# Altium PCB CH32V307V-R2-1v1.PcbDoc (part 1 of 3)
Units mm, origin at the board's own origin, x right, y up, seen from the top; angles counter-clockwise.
Board outline 80 x 115 mm, 2 copper layers (Top Layer, Bottom Layer); 122 components, 134 nets, 559 pads, 721 vias.
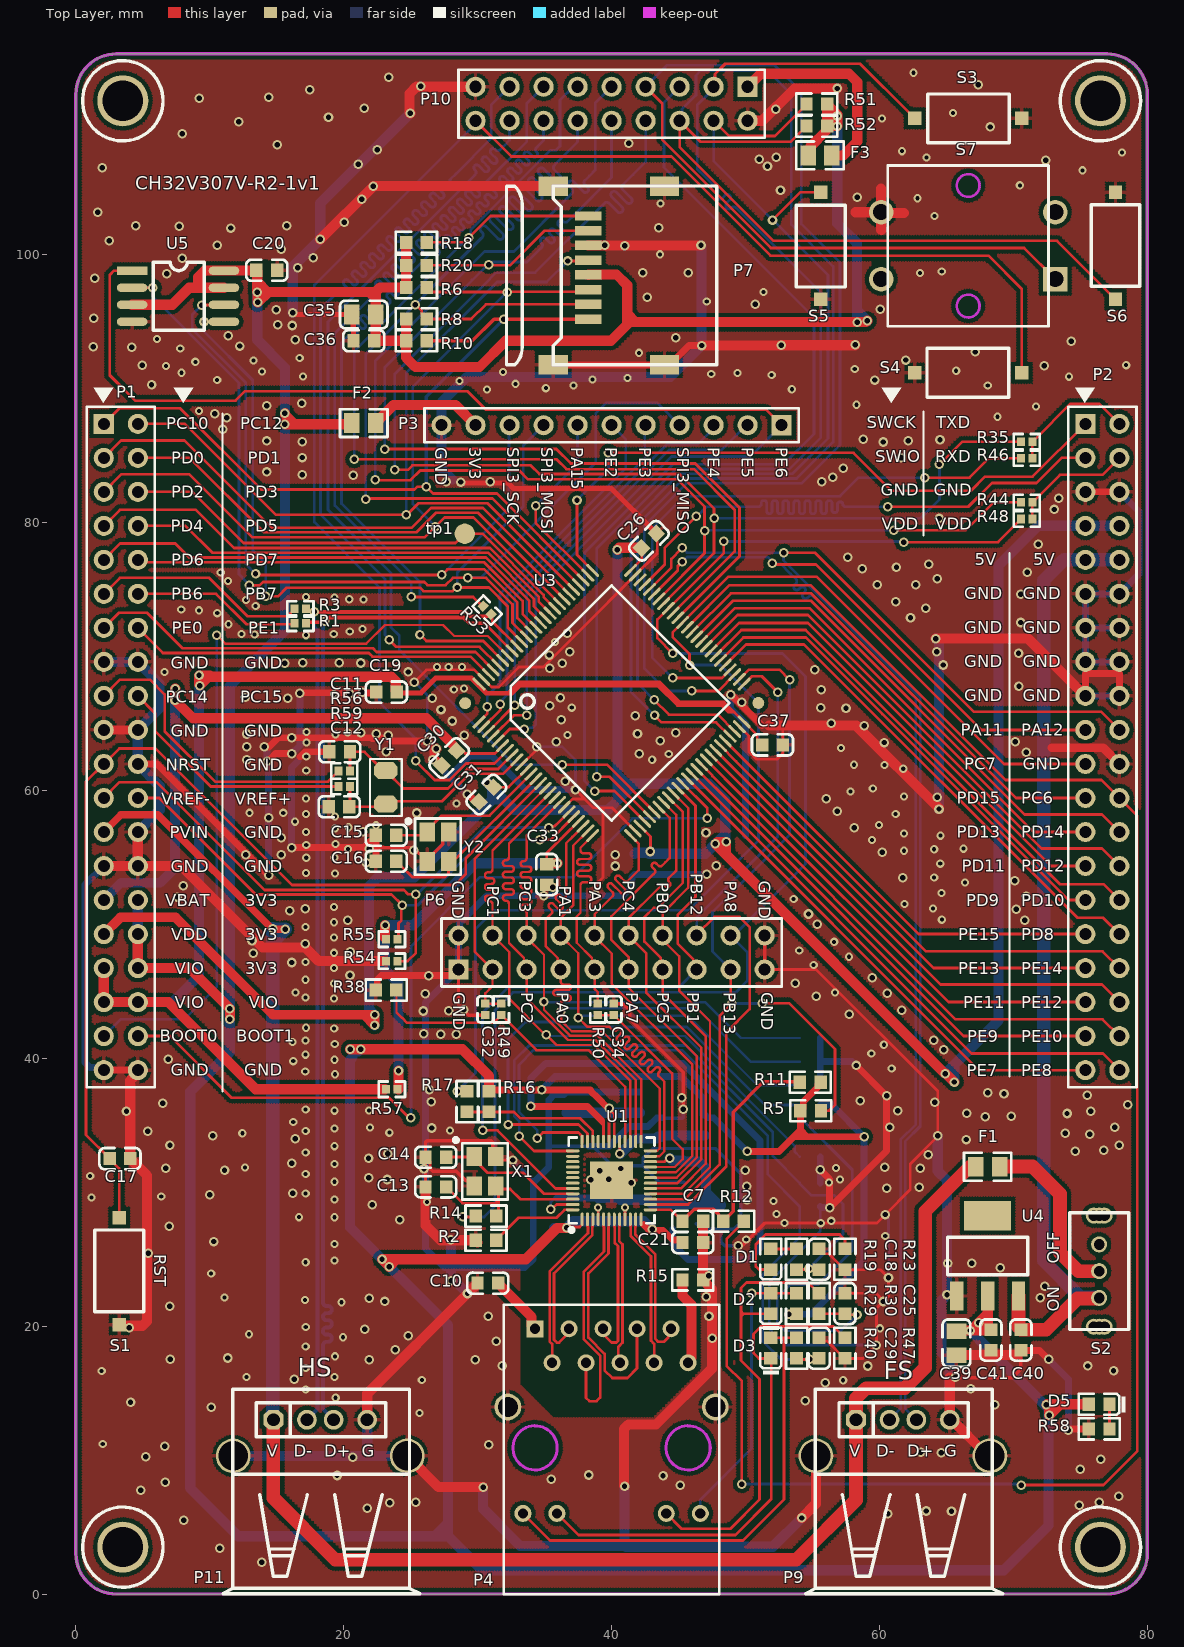
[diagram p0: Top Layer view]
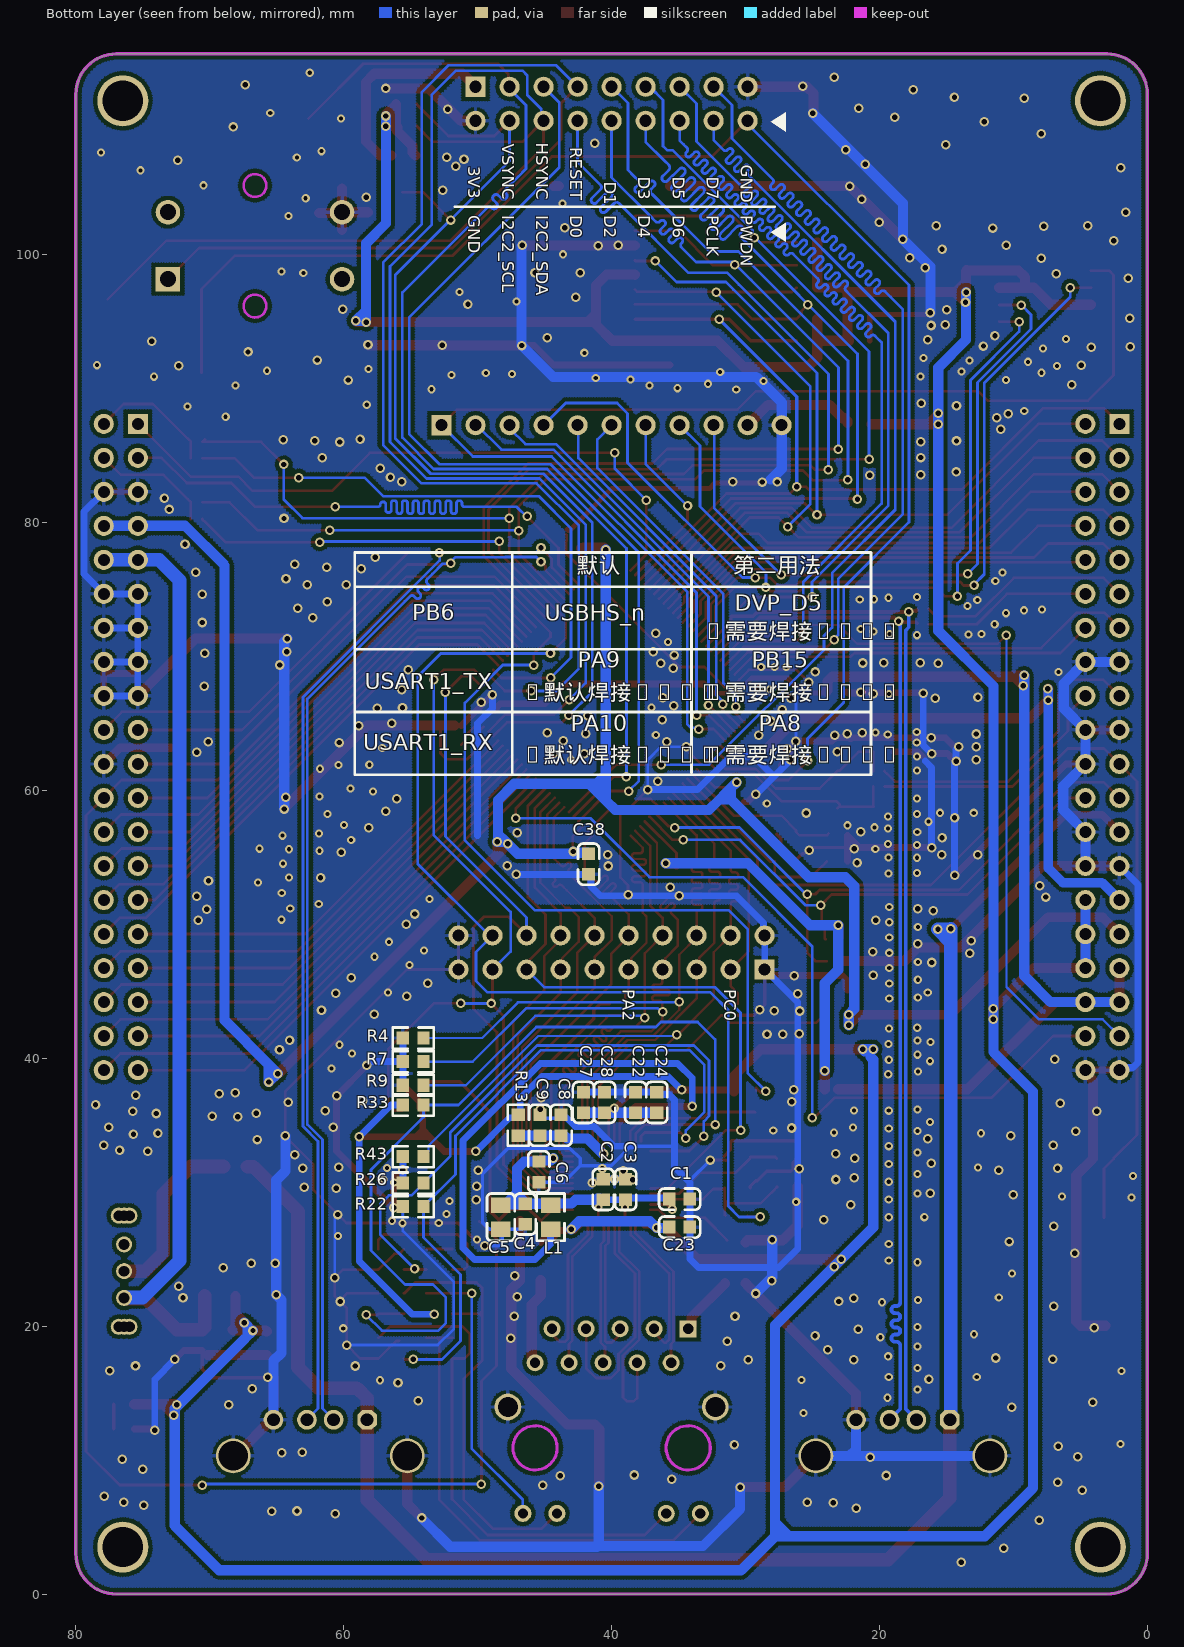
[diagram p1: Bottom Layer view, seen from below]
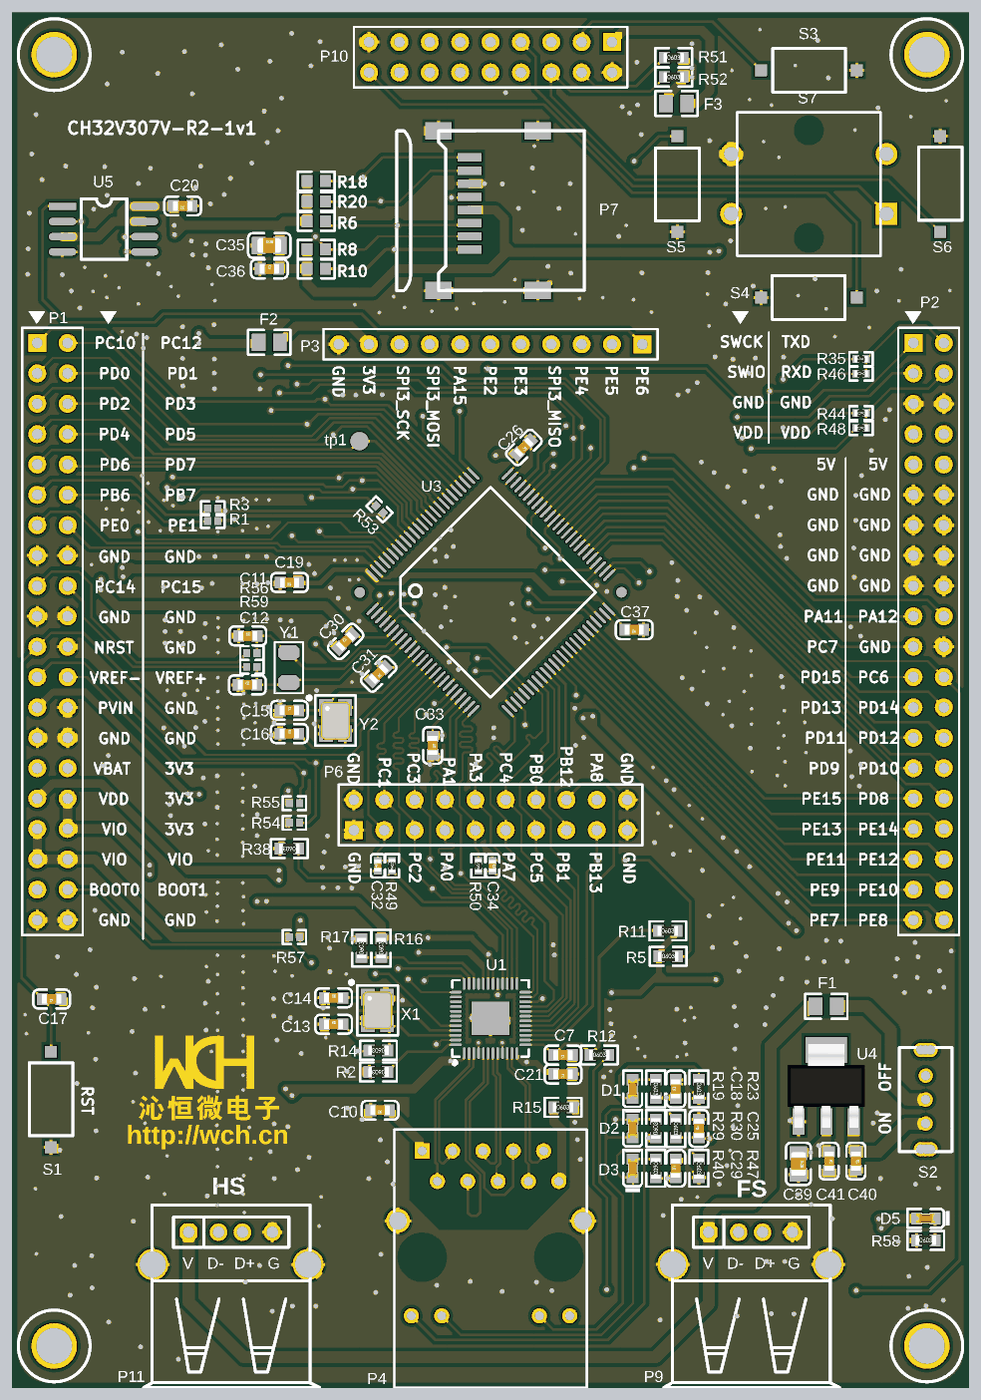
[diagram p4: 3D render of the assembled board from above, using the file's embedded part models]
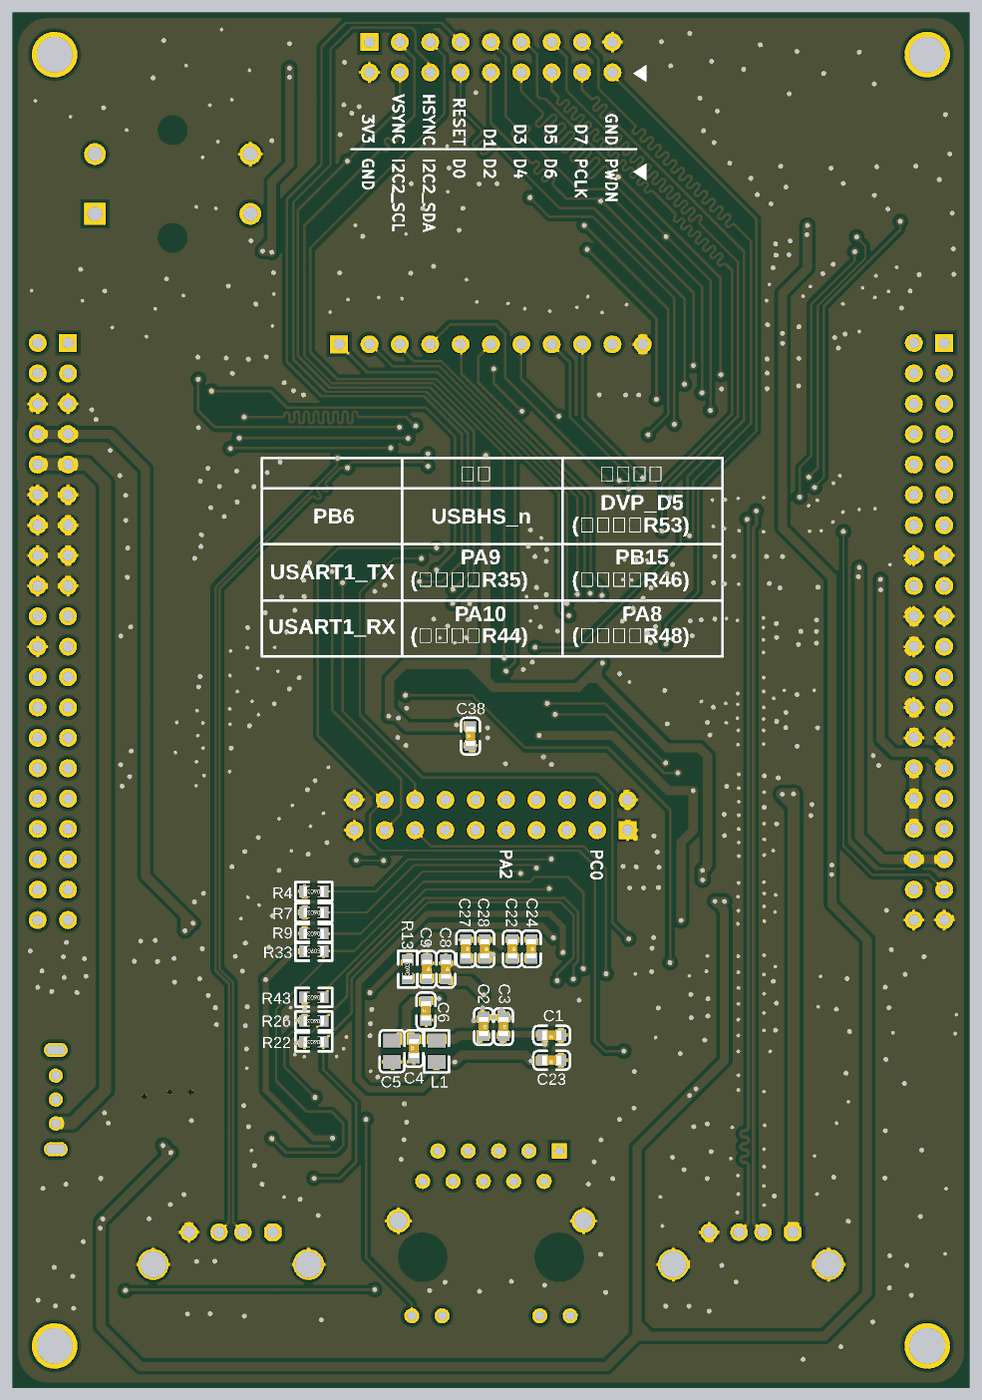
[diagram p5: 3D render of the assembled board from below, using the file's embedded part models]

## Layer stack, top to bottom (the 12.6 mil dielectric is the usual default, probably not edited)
Top Solder: solder mask 0.0102, Solder Resist, Dk 3.5
Top Layer: signal copper 0.0356
Dielectric 1: dielectric 0.32, FR-4, Dk 4.8
Bottom Layer: signal copper 0.0356
Bottom Solder: solder mask 0.0102, Solder Resist, Dk 3.5

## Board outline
0,3 0,112 cw(c3,112) 3,115 77.007,115 77,115 cw(c77,112) 80,112 80,2.999 80,3 cw(c77,3) 77,0 3,0 cw(c3,3)

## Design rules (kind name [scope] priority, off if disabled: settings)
Clearance Clearance_2 [InPolygon] p1: gap=0.305 ignorepadtopadclearanceinfootprint=FALSE
Clearance [All] p2: gap=0.127 ignorepadtopadclearanceinfootprint=FALSE except(0.178: Arc-Via Track-Via SMDPad-Via THPad-Via Via-Via Via-Fill Via-Poly Via-Region Via-Text Via-Hole)
ComponentClearance [All] p1 off: gap=0.254 collisioncheckmode=3 verticalgap=0.254 showdistances=FALSE
DiffPairsRouting [All] p1: maxlimit=0.254 minlimit=0.127 mostfreqgap=0.254 toplayer_minwidth=0.152 toplayer_maxwidth=0.381 toplayer_prefwidth=0.381 bottomlayer_minwidth=0.152 bottomlayer_maxwidth=0.381 bottomlayer_prefwidth=0.381 maxuncoupledlength=12.7
MinimumSolderMaskSliver [All] p1 off: minsoldermaskwidth=0.254
PolygonConnect PolygonConnect_1 [IsVia] p1: connectstyle=Direct reliefconductorwidth=0.254 reliefentries=4 polygonreliefangle="90 Angle" airgapwidth=0.254
PolygonConnect [All] p2: connectstyle=Relief reliefconductorwidth=0.254 reliefentries=4 polygonreliefangle="90 Angle" airgapwidth=0.254
RoutingVias [All] p1: holewidth=0.711 width=1.27 viastyle="Through Hole" minholewidth=0.305 minwidth=0.61 maxholewidth=0.711 maxwidth=1.27
SilkToSilkClearance [All] p1 off: silktosilkclearance=0.254
SilkToSolderMaskClearance [IsPad] p1 off: minsilkscreentomaskgap=0.254 clearancetoexposedcopper=TRUE
SolderMaskExpansion [All] p1: expansion=0.102 istentingtop=FALSE
Width [All] p1: maxlimit=2.54 minlimit=0.127 preferedwidth=0.254
25 further rules are at their usual default settings.

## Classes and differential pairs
differential pair USB1D: +USB1D_p -USB1D_n
differential pair USB2D: +USB2D_p -USB2D_n
differential pair MDI3: +MDI3_p -MDI3_n
differential pair MDI2: +MDI2_p -MDI2_n
differential pair MDI1: +MDI1_p -MDI1_n
differential pair MDI0: +MDI0_p -MDI0_n

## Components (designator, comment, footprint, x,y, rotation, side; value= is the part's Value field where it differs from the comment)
C1 "100nF" 0603_C 34.921,29.489 r0 bottom
C2 "100nF" 0603_C 40.623,30.217 r270 bottom
C3 "100nF" 0603_C 38.953,30.217 r270 bottom
C4 "100nF" 0603_C 46.444,28.377 r90 bottom
C5 "22uF" 0805_C#1 48.271,27.252 r90 bottom
C6 "100nF" 0603_C 45.433,31.527 r90 bottom
C7 "100nF" 0603_C 46.062,27.833 r180 top
C8 "100nF" 0603_C 43.773,35.004 r270 bottom
C9 "4.7uF" 0603_C 45.357,35.004 r270 bottom
C10 "100nF" 0603_C 30.756,23.212 r180 top
C11 "12pF" 0603_C 19.698,62.889 r0 top
C12 "12pF" 0603_C 19.657,58.786 r0 top
C13 "27pF" 0603_C 26.873,30.404 r0 top
C14 "27pF" 0603_C 26.873,32.614 r0 top
C15 "20pF" 0603_C 23.167,56.655 r0 top
C16 "20pF" 0603_C 23.167,54.719 r0 top
C17 "100nF" 0603_C 3.285,32.513 r180 top
C18 "100nF" 0603_C 55.495,24.995 r90 top
C19 "100nF" 0603_C 23.186,67.348 r180 top
C20 "100nF" 0603_C 14.251,98.843 r180 top
C21 "100nF" 0603_C 46.062,26.241 r180 top
C22 "100nF" 0603_C 38.206,36.708 r270 bottom
C23 "100nF" 0603_C 34.921,27.397 r0 bottom
C24 "4.7uF" 0603_C 36.628,36.708 r270 bottom
C25 "100nF" 0603_C 57.427,21.691 r90 top
C26 "100nF" 0603_C 42.788,78.647 r225 top
C27 "100nF" 0603_C 42.099,36.708 r270 bottom
C28 "4.7uF" 0603_C 40.521,36.708 r270 bottom
C29 "100nF" 0603_C 55.495,18.359 r90 top
C30 "100nF" 0603_C 27.879,62.42 r45 top
C31 "100nF" 0603_C 30.646,59.701 r225 top
C32 "NC" 0402_C 30.564,43.656 r90 top
C33 "100nF" 0603_C 35.157,53.724 r270 top
C34 "NC" 0402_C 40.165,43.656 r270 top
C35 "10uF" 0805_C#2 21.492,95.537 r0 top
C36 "0.1uF" 0603_C 21.498,93.583 r0 top
C37 "100nF" 0603_C 52.014,63.403 r180 top
C38 "100nF" 0603_C 41.718,54.502 r90 bottom
C39 "10uF" 0805_C#2 65.749,18.729 r270 top
C40 "100nF" 0603_C 70.563,18.964 r270 top
C41 "100nF" 0603_C 68.318,18.964 r270 top
D1 "蓝灯 0603" 0603_LED_S1 51.886,24.995 r90 top
D2 "黄灯 0805" 0603_LED_S1 51.886,21.691 r90 top
D3 "翠绿 0805" 0603_LED_S1 51.886,18.359 r90 top
D5 "蓝灯 0603" 0603_LED_S1 76.408,14.168 r180 top
F1 "500mA" 0805 67.191,31.903 r0 top
F2 "200mA" 0805 22.382,87.434 r180 top
F3 "100mA" 0805 56.447,107.419 r180 top
L1 "22uH" 0805 44.546,27.252 r90 bottom
P1 "Header 20X2" HDR2X20 2.081,87.38 r270 top
P2 "Header 20X2" HDR2X20 75.379,87.38 r270 top
P3 "Header 11" HDR1X11 52.7,87.274 r180 top
P4 "HR911130C" RJ45-1G 34.283,19.807 r180 top locked
P6 "Header 10X2" HDR2X10 28.57,46.634 r0 top
P7 "TF CARD" TF103 38.253,95.212 r180 top
P9 "USB" USBAF 58.253,13.012 r0 top
P10 "Header 9X2" HDR2X9 50.16,112.547 r180 top
P11 "USB" USBAF 14.747,13.012 r0 top
R1 "0Ω (0R0) ±1%" 0402 17.186,72.489 r180 top
R2 "2.49K 1%" 0603_R 30.619,26.416 r180 top
R3 "0Ω (0R0) ±1%" 0402 17.186,73.562 r180 top
R4 "4.7K" 0603_R 54.814,41.515 r0 bottom
R5 "4.7K" 0603_R 54.865,36.086 r0 top
R6 "47K" 0603_R 25.422,97.549 r180 top
R7 "4.7K" 0603_R 54.814,39.753 r0 bottom
R8 "47K" 0603_R 25.422,95.212 r180 top
R9 "4.7K" 0603_R 54.814,37.992 r0 bottom
R10 "47K" 0603_R 25.422,93.583 r180 top
R11 "4.7K" 0603_R 54.831,38.216 r0 top
R12 "0Ω" 0603_R 49.105,27.833 r0 top
R13 "0Ω" 0603_R 46.97,35.004 r90 bottom
R14 "0Ω" 0603_R 30.619,28.219 r180 top
R15 "0Ω" 0603_R 46.062,23.455 r0 top
R16 "4.7K" 0603_R 30.856,36.77 r90 top
R17 "0Ω(NC)" 0603_R 29.205,36.77 r90 top
R18 "47K" 0603_R 25.422,100.926 r180 top
R19 "0Ω" 0603_R 53.817,24.995 r270 top
R20 "47K" 0603_R 25.422,99.213 r180 top
R22 "4.7K" 0603_R 54.814,28.93 r0 bottom
R23 "510Ω" 0603_R 57.427,24.995 r270 top
R26 "4.7K" 0603_R 54.814,30.681 r0 bottom
R29 "510Ω" 0603_R 53.817,21.691 r90 top
R30 "0Ω" 0603_R 55.495,21.691 r270 top
R33 "4.7K" 0603_R 54.814,36.513 r180 bottom
R35 "0Ω (0R0) ±1%" 0402_R 70.991,86.037 r180 top
R38 "4.7K" 0603_R 23.167,45.098 r180 top
R40 "0Ω" 0603_R 53.817,18.359 r270 top
R43 "4.7K" 0603_R 54.814,32.656 r0 bottom
R44 "0Ω (0R0) ±1%" 0402_R 70.991,81.518 r180 top
R46 "0Ω (0R0) ±1%" 0402_R 70.991,84.811 r180 top
R47 "510Ω" 0603_R 57.427,18.359 r270 top
R48 "0Ω (0R0) ±1%" 0402_R 70.991,80.265 r180 top
R49 "0Ω" 0402_R 31.758,43.656 r90 top
R50 "0Ω" 0402_R 38.971,43.656 r90 top
R51 "10KΩ (1002) ±1%" 0603_R 55.322,111.252 r0 top
R52 "10KΩ (1002) ±1%" 0603_R 55.322,109.615 r0 top
R53 "0Ω (0R0) ±1%" 0402 31.008,73.16 r135 top
R54 "0R" 0402 23.167,47.26 r0 top
R55 "0R" 0402 23.167,48.891 r0 top
R56 "0Ω (0R0) ±1%" 0402 20.468,61.452 r180 top
R57 "0R" 0402 23.167,37.691 r0 top
R58 "470Ω (4700) ±1%" 0603_R 76.408,12.329 r0 top
R59 "0Ω (0R0) ±1%" 0402 20.468,60.293 r180 top
S1 "RST#" SMD_6.1x3.65x2.5mm-KEY 3.233,20.106 r90 top
S2 "SW SPDT" "Horizontal Slide Switch_8.7x4.4mm-2D" 78.603,19.756 r90 top
S3 "up" SMD_6.1x3.65x2.5mm-KEY 62.626,110.182 r0 top
S4 "down" SMD_6.1x3.65x2.5mm-KEY 70.626,91.182 r180 top
S5 "left" SMD_6.1x3.65x2.5mm-KEY 55.627,104.674 r270 top
S6 "right" SMD_6.1x3.65x2.5mm-KEY 77.626,96.674 r90 top
S7 "OK" KEYD 73.126,98.183 r180 top locked
tp1 "test-point" POINT 29.031,79.174 r0 top
U1 "RTL8211FS" QFN-48_6x6x04P 40,30.886 r0 top
U3 "CH32V307V" LQFP100 30.101,65.118 r315 top
U4 "LM1117" SOT-223 68.081,25.254 r270 top
U5 "W25Q32JV" SOIC-8_208mil 4.196,98.811 r270 top
X1 "25MHz" SMD-3225_4P 30.546,31.566 r270 top
Y1 "32768Hz" FC-135 23.137,61.474 r270 top
Y2 "8MHz" SMD-3225_4P 27.027,55.803 r270 top
? "" HOLE 76.5,3.5 r0 top
? "" HOLE 3.5,3.5 r0 top
? "" HOLE 3.5,111.5 r0 top
? "" HOLE 76.5,111.5 r0 top

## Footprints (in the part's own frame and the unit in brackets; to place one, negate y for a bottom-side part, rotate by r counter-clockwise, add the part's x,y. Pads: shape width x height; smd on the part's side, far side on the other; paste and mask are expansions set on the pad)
0402 [mm]
  rect 0.6x0.65 smd mask+0.051: 1(0,0) 2(0.85,0)
  silkscreen extent -0.55,-0.58 1.4,0.57
0402_C [mm]
  rect 0.6x0.65 smd mask+0.051: 1(-0.425,0) 2(0.425,0)
  silkscreen extent -0.97,-0.58 0.98,0.58, body extent -0.48,-0.3 0.52,0.3, height 0.2
0402_R [mm]
  rect 0.6x0.65 smd mask+0.051: 1(-0.425,0) 2(0.425,0)
  silkscreen extent -0.98,-0.58 0.98,0.58, body extent -0.57,-0.27 0.58,0.28, height 0.41
0603_C [mm]
  rect 0.93x0.98 smd: 1(-0.77,0) 2(0.77,0)
  silkscreen extent -1.53,-0.79 1.54,0.79, body extent -0.8,-0.4 0.8,0.4, height 0.3
0603_LED_S1 [mm]
  rect 0.93x0.98 smd: A(0.77,0) K(-0.77,0)
  silkscreen extent -1.97,-0.79 1.54,0.79, body extent -0.8,-0.4 0.8,0.4, height 0.6
0603_R [mm]
  rect 0.93x0.98 smd: 1(-0.77,0) 2(0.77,0)
  silkscreen extent -1.53,-0.79 1.54,0.79, body extent -0.85,-0.4 0.85,0.4, height 0.56
0805 [mm]
  rect 1.16x1.47 smd: 1(0,0) 2(1.78,0)
  silkscreen extent -0.88,-1.04 2.66,1.03
0805_C#1 [mm]
  rect 1.16x1.47 smd: 1(0,0) 2(1.78,0)
  silkscreen extent -0.88,-1.04 2.66,1.03
0805_C#2 [mm]
  rect 1.16x1.47 smd: 1(-0.89,0) 2(0.89,0)
  silkscreen extent -1.77,-1.04 1.77,1.04, body extent -1,-0.62 1,0.63, height 0.77
FC-135 [mil]
  oct 50x70 smd: 1(0,0) 2(98.43,0)
  silkscreen extent -35,-47 133,47
HDR1X11 [mm] "Connector; Header; 11 Position"
  rect 1.5x1.5 hole 0.9: 1(0,0)
  round 1.5 hole 0.9: 2(2.54,0) 3(5.08,0) 4(7.62,0) 5(10.16,0) 6(12.7,0) 7(15.24,0) 8(17.78,0) 9(20.32,0) 10(22.86,0) 11(25.4,0)
  silkscreen extent -1.27,-1.27 26.67,1.27
HDR2X9 [mm] "Connector; Header; 9x2 Position"
  rect 1.5x1.5 hole 0.9: 1(0,0)
  round 1.5 hole 0.9: 2(0,2.54) 3(2.54,0) 4(2.54,2.54) 5(5.08,0) 6(5.08,2.54) 7(7.62,0) 8(7.62,2.54) 9(10.16,0) 10(10.16,2.54) 11(12.7,0) 12(12.7,2.54) 13(15.24,0) 14(15.24,2.54) 15(17.78,0) 16(17.78,2.54) 17(20.32,0) 18(20.32,2.54)
  silkscreen extent -1.27,-1.27 21.59,3.81
HDR2X10 [mm] "Connector; Header; 10x2 Position"
  rect 1.5x1.5 hole 0.9: 1(0,0)
  round 1.5 hole 0.9: 2(0,2.54) 3(2.54,0) 4(2.54,2.54) 5(5.08,0) 6(5.08,2.54) 7(7.62,0) 8(7.62,2.54) 9(10.16,0) 10(10.16,2.54) 11(12.7,0) 12(12.7,2.54) 13(15.24,0) 14(15.24,2.54) 15(17.78,0) 16(17.78,2.54) 17(20.32,0) 18(20.32,2.54) 19(22.86,0) 20(22.86,2.54)
  silkscreen extent -1.27,-1.27 24.13,3.81
HDR2X20 [mm] "Connector; Header; 20x2 Position"
  rect 1.5x1.5 hole 0.9: 1(0,0)
  round 1.5 hole 0.9: 2(0,2.54) 3(2.54,0) 4(2.54,2.54) 5(5.08,0) 6(5.08,2.54) 7(7.62,0) 8(7.62,2.54) 9(10.16,0) 10(10.16,2.54) 11(12.7,0) 12(12.7,2.54) 13(15.24,0) 14(15.24,2.54) 15(17.78,0) 16(17.78,2.54) 17(20.32,0) 18(20.32,2.54) 19(22.86,0) 20(22.86,2.54) 21(25.4,0) 22(25.4,2.54) 23(27.94,0) 24(27.94,2.54) 25(30.48,0) 26(30.48,2.54) 27(33.02,0) 28(33.02,2.54) 29(35.56,0) 30(35.56,2.54) 31(38.1,0) 32(38.1,2.54) 33(40.64,0) 34(40.64,2.54) 35(43.18,0) 36(43.18,2.54) 37(45.72,0) 38(45.72,2.54) 39(48.26,0) 40(48.26,2.54)
  silkscreen extent -1.27,-1.27 49.53,3.81
HOLE [mm]
  round 3.81 hole 3: 0(0,0)
  silkscreen extent -3,-3 3,3
"Horizontal Slide Switch_8.7x4.4mm-2D" [mm]
  round 1.2 hole 0.8: 0(0.2,2.6) 0(0.2,2.2) 0(0.2,1.8) 0(8.5,1.8) 0(8.5,2.2) 0(8.5,2.6) 1(4.35,2.2) 2(2.35,2.2) 3(6.35,2.2)
  silkscreen extent 0,0 8.7,4.4
KEYD [mm]
  rect 1.829x1.829 hole 1.2: 1(0,0)
  round 1.829 hole 1.2: 2(0,-5) 3(13,-5) 4(13,0)
  Keep-Out Layer circle w0.2: c6.5,-6.991 r0.85
  Keep-Out Layer circle w0.2: c6.5,2.009 r0.85
  silkscreen extent 0.5,-8.49 12.5,3.51
LQFP100 [mil]
  round 35 smd: 0(-68,10) 0(541.18,620)
  rect 9x50 smd: 1(0,0)
  oval 9x50 smd: 2(19.69,0) 3(39.37,0) 4(59.06,0) 5(78.74,0) 6(98.43,0) 7(118.11,0) 8(137.8,0) 9(157.48,0) 10(177.17,0) 11(196.85,0) 12(216.54,0) 13(236.22,0) 14(255.91,0) 15(275.59,0) 16(295.28,0) 17(314.96,0) 18(334.64,0) 19(354.33,0) 20(374.01,0) 21(393.7,0) 22(413.38,0) 23(433.07,0) 24(452.75,0) 25(472.44,0) 51(472.44,629.92) 52(452.75,629.92) 53(433.07,629.92) 54(413.39,629.92) 55(393.7,629.92) 56(374.02,629.92) 57(354.33,629.92) 58(334.65,629.92) 59(314.96,629.92) 60(295.27,629.92) 61(275.59,629.92) 62(255.9,629.92) 63(236.22,629.92) 64(216.54,629.92) 65(196.85,629.92) 66(177.17,629.92) 67(157.48,629.92) 68(137.8,629.92) 69(118.11,629.92) 70(98.43,629.92) 71(78.74,629.92) 72(59.06,629.92) 73(39.37,629.92) 74(19.69,629.92) 75(0,629.92)
  oval 50x9 smd: 26(551.18,78.74) 27(551.18,98.43) 28(551.18,118.11) 29(551.18,137.8) 30(551.18,157.48) 31(551.18,177.17) 32(551.18,196.85) 33(551.18,216.54) 34(551.18,236.22) 35(551.18,255.91) 36(551.18,275.59) 37(551.18,295.28) 38(551.18,314.96) 39(551.18,334.65) 40(551.18,354.33) 41(551.18,374.02) 42(551.18,393.7) 43(551.18,413.39) 44(551.18,433.07) 45(551.18,452.76) 46(551.18,472.44) 47(551.18,492.13) 48(551.18,511.81) 49(551.18,531.5) 50(551.18,551.18) 76(-78.74,551.18) 77(-78.74,531.5) 78(-78.74,511.81) 79(-78.74,492.13) 80(-78.74,472.44) 81(-78.74,452.76) 82(-78.74,433.07) 83(-78.74,413.39) 84(-78.74,393.7) 85(-78.74,374.02) 86(-78.74,354.33) 87(-78.74,334.65) 88(-78.74,314.96) 89(-78.74,295.28) 90(-78.74,275.59) 91(-78.74,255.91) 92(-78.74,236.22) 93(-78.74,216.54) 94(-78.74,196.85) 95(-78.74,177.17) 96(-78.74,157.48) 97(-78.74,137.8) 98(-78.74,118.11) 99(-78.74,98.43) 100(-78.74,78.74)
  silkscreen extent -8,70 481,560
POINT [mil] "测试点"
  round 60 smd: 1(0,0)
QFN-48_6x6x04P [mm]
  rect 3.2x2.8 smd mask+0.051: 0(0,0)
  oval 0.22x1 smd mask+0.051: 1(-2.2,-2.9) 2(-1.8,-2.9) 3(-1.4,-2.9) 4(-1,-2.9) 5(-0.6,-2.9) 6(-0.2,-2.9) 7(0.2,-2.9) 8(0.6,-2.9) 9(1,-2.9) 10(1.4,-2.9) 11(1.8,-2.9) 12(2.2,-2.9) 25(2.2,2.9) 26(1.8,2.9) 27(1.4,2.9) 28(1,2.9) 29(0.6,2.9) 30(0.2,2.9) 31(-0.2,2.9) 32(-0.6,2.9) 33(-1,2.9) 34(-1.4,2.9) 35(-1.8,2.9) 36(-2.2,2.9)
  oval 1x0.22 smd mask+0.051: 13(2.9,-2.2) 14(2.9,-1.8) 15(2.9,-1.4) 16(2.9,-1) 17(2.9,-0.6) 18(2.9,-0.2) 19(2.9,0.2) 20(2.9,0.6) 21(2.9,1) 22(2.9,1.4) 23(2.9,1.8) 24(2.9,2.2) 37(-2.9,2.2) 38(-2.9,1.8) 39(-2.9,1.4) 40(-2.9,1) 41(-2.9,0.6) 42(-2.9,0.2) 43(-2.9,-0.2) 44(-2.9,-0.6) 45(-2.9,-1) 46(-2.9,-1.4) 47(-2.9,-1.8) 48(-2.9,-2.2)
  silkscreen extent -3.2,-3.85 3.2,3.2
RJ45-1G [mil]
  round 78.74 hole 59.06: 0(-529.99,229.92) 0(79.85,229.92)
  rect 50x50 hole 30: 1(0,0)
  round 50 hole 30: 2(-50,100) 3(-100,0) 4(-150,100) 5(-200,0) 6(-250,100) 7(-300,0) 8(-350,100) 9(-400,0) 10(-450,100) 11(35.76,542.91) 12(-64.24,542.91) 13(-385.9,542.91) 14(-485.9,542.91)
  Keep-Out Layer circle w9: c0,350 r65
  Keep-Out Layer circle w9: c-450,350 r65
  silkscreen extent -542,-70 92,780
SMD-3225_4P [mm]
  rect 1.4x1.15 smd: 1(-1.1,-0.8) 2(1.1,-0.8) 3(1.1,0.8) 4(-1.1,0.8)
  silkscreen extent -2.48,-2.32 2.1,1.7, body extent -1.6,-1.25 1.6,1.25, height 0.61
SMD_6.1x3.65x2.5mm-KEY [mm]
  rect 1x1 smd: 1(0,0) 2(8,0)
  silkscreen extent 0.98,-1.82 7.08,1.82
SOIC-8_208mil [mil]
  rect 24x90 smd: 1(0,0)
  oval 24x90 smd: 2(50,0) 3(100,0) 4(150,0) 5(150,270) 6(100,270) 7(50,270) 8(0,270)
  silkscreen extent -25,62 175,212
SOT-223 [mm]
  rect 2.2x1 smd: 1(3,-2.3) 2(3,0) 3(3,2.3)
  rect 2.2x3.5 smd: 2(-3,0)
  silkscreen extent -1.4,-3 1.4,3, body extent -3.49,-3.24 3.49,3.24, height 1.64
TF103 [mm]
  rect 2x0.7 smd: 1(0.003,0.011) 2(0.003,-1.089) 3(0.003,-2.189) 4(0.003,-3.289) 5(0.003,-4.389) 6(0.003,-5.489) 7(0.003,-6.589) 8(0.003,-7.689)
  rect 2.2x1.45 smd: 10(-5.697,3.436) 10(-5.697,-9.914) 10(2.603,3.436) 10(2.603,-9.914)
  silkscreen extent -9.6,-9.92 6.1,3.44
USBAF [mil]
  round 102.36 hole 86.61: 0(-118.11,-106.3) 0(393.7,-106.3)
  oct 58x58 hole 38: 1(0,0)
  round 58 hole 38: 2(98.43,0) 3(177.17,0) 4(275.59,0)
  silkscreen extent -148,-511 431,90

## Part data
C1 C2 C3 C4 C5 C6 C7 C8 C9 C10 C11 C12 C13 C14 C15 C16 C17 C18 C19 C20 C21 C22 C23 C24 C25 C26 C27 C28 C29 C30 C31 C33 C37 C38 C39 C40 C41: library part CAP, "Capacitor"
C32 C34: library part "0603 2.7pF (2R7) 0.25pF 50V", "贴片电容", Package=0603, SuppliersPartNumber=C16149
C35 C36: library part Cap, "Capacitor"
D1 D5: library part "0603 蓝灯", "发光二极管", Package=0603, SuppliersPartNumber=C72041
D2: library part "0805 黄灯", "发光二极管", Package=0805, SuppliersPartNumber=C2296
D3: library part "0805 翠绿", "发光二极管", Package=0805, SuppliersPartNumber=C2297
F1 F2 F3: library part "Fuse 1", "Fuse"
L1: library part Inductor, "Inductor"
P1 P2: "Header, 20-Pin, Dual row"
P3: "Header, 11-Pin"
P6: "Header, 10-Pin, Dual row"
P7: library part TF_自弹
P9 P11: "USB Port"
P10: "Header, 9-Pin, Dual row"
R1 R3 R35 R44 R46 R48 R53 R56 R59: library part "0402 0Ω (0R0) 1%", "贴片电阻", Package=0402, SuppliersPartNumber=C17168
R2 R4 R5 R7 R9 R11 R12 R13 R14 R15 R16 R17 R19 R22 R23 R26 R29 R30 R33 R38 R40 R43 R47: library part Res
R6 R8 R10 R18 R20 R49 R50: library part Res2, "Resistor"
R51 R52: library part "0603 10KΩ (1002) 1%", "贴片电阻", Package=0603, SuppliersPartNumber=C25804
R54 R55 R57: library part R
R58: library part "0603 470Ω (4700) 1%", "贴片电阻", Package=0603, SuppliersPartNumber=C23179
S1 S3 S4 S5 S6 S7: library part KEY1
tp1: "测试点"
U1: library part RTL8211FS(I), "千兆以太网物理层芯片"
U3: "RISC-V FPU HD-MCU, 144MHz, USB_480M, USB OTG, 1000M Ethernet MAC, 2*CAN, FSMC+DVP"
U4: library part 6219P33M
U5: library part Pro89C.tmp_25F512_2
X1: library part XTAL-2P, "2脚无源脚晶振"
Y1 Y2: library part XTAL, "Crystal Oscillator"

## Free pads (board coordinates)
  round 0.711 hole 0.406: 2(39.782,30.987)

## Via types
v1: diameter 0.711, hole 0.406, Top Layer to Bottom Layer, tented both sides, 507 vias
v2: diameter 0.61, hole 0.305, Top Layer to Bottom Layer, tented both sides, 214 vias

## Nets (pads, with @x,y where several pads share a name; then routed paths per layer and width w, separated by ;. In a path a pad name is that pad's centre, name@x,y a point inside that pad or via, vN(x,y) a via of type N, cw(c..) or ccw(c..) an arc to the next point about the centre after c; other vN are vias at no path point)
3V3: C20.2 C21.2 C22.2 C23.2 C24.2 C27.2 C28.2 C35.2 C36.2 C39.1 C41.1 D5.A F2.2 F3.2 P1.30 P1.32 P1.34 P7.4 R5.1 R6.2 R8.2 R10.2 R11.2 R13.2 R16.2 R18.2 R20.2 R29.1 R33.1 R51.2 R52.2 U1.1 U1.12 U1.30 U1.31 U4.2@68.081,22.254 U5.3 U5.7 U5.8 | length 486.5
  Top Layer w0.203: v1(36.646,27.34) 36.713,27.407 37.615,27.407 37.8,27.592 U1.1@37.8,27.986 ; 39.304,36.693 v1@39.8,36.196 ; U1.31@39.8,33.786 v1@39.8,36.196 ; U1.30@40.2,33.786 40.203,33.79 40.203,35.793 v1@39.8,36.196
  Top Layer w0.508: R16.2@30.856,37.54 30.957,37.642 34.134,37.642 38.431,37.642 38.355,37.642 ; v1(34.768,37.642) 38.355,37.642 ; v1@39.79,36.206 39.79,36.227 39.659,36.358 39.638,36.358 39.043,36.953 38.355,37.642 ; 42.376,27.583 42.624,27.335 42.807,27.152 43.842,27.152 44.567,26.427 45.106,26.427 C21.2@45.292,26.241 ; v1(50.128,33.049) 52.494,33.049 53.583,34.138 ; R11.2@55.601,38.216 55.39,38.005 55.39,37.818 54.306,36.733 54.306,36.297 R5.1@54.095,36.086 54.095,34.65 ; v1(58.85,34.138) 54.607,34.138 ; 53.583,34.138 54.095,34.65 ; 53.583,34.138 54.607,34.138 ; 54.095,34.65 54.607,34.138
  Top Layer w0.762: U5.3@4.196,96.271 7.193,96.271 8.463,97.541 U5.7@11.054,97.541 ; P1.32@4.621,49.28 P1.34@4.621,46.74 8.465,46.74 v1(11.488,43.718) 11.497,43.709 v1@11.497,42.97 ; 9.126,97.746 9.126,98.329 9.625,98.827 C20.2@13.465,98.827 ; C20.2@13.481,98.843 C20.2@13.465,98.827 ; v1(15.607,88.182) v1@15.607,88.043 ; 16.204,87.446 v1@15.607,88.043 ; v1(20.469,40.683) 28.856,40.683 30.856,38.683 R16.2@30.856,37.54 ; F2.2@20.602,87.351 v1(15.607,87.351) v1@15.607,88.043 ; C36.2@22.269,93.583 C36.2@22.288,93.583 ; R8.2@24.652,95.212 R10.2@24.652,93.583 ; R18.2@24.652,100.901 R20.2@24.652,99.213 R6.2@24.652,97.549 24.586,97.549 24.568,97.568 22.717,97.568 22.382,97.233 22.382,97.216 ; v1(36.646,27.34) 35.941,27.34 33.599,24.999 23.941,24.999 ; P7.4@38.25,98.501 38.275,98.526 40.368,98.526 41.163,97.731 41.163,95.593 ; F3.2@54.652,107.419 54.866,107.633 54.866,108.105 56.008,109.247 56.008,109.531 R52.2@56.092,109.615 ; R51.2@56.092,111.252 R51.2@56.092,111.227 ; v1(59.096,95.069) 59.001,94.974 v1(58.333,94.974) 42.624,94.974 41.782,94.974 ; C39.1@65.749,19.619 65.807,19.676 v1(66.778,19.676) v1@66.832,19.676 ; U4.2@68.081,22.254 68.081,20.925 ; D5.A@75.638,14.168 73.499,14.168 ; C20.2@13.465,98.827 13.534,98.759 13.534,97.987 ; v1(13.534,97.216) 14.305,97.216 ; v1(13.534,97.216) 13.534,97.987 ; v1(13.534,97.216) 13.574,97.176 v1(13.574,96.44) 14.35,97.216 ; 13.534,97.987 14.305,97.216 ; 14.305,97.216 14.35,97.216 ; 14.35,97.216 21.943,97.216 ; 21.943,97.216 22.382,97.216 ; 21.943,97.216 22.382,96.777 ; C36.2@22.288,93.583 R10.2@24.652,93.583 ; C36.2@22.288,93.583 22.382,93.678 C35.2@22.382,95.537 22.382,96.777 ; 22.382,96.777 22.382,97.216 ; 23.941,24.999 v1(22.857,24.999) 23.386,24.47 v1(23.386,24.444) 23.941,24.999 ; R10.2@24.652,93.583 24.652,92.324 25.35,91.625 30.14,91.625 32.101,93.587 39.955,93.587 41.163,94.795 ; 41.163,94.795 41.163,95.593 ; 41.163,94.795 41.342,94.974 41.782,94.974 ; 41.163,95.593 41.782,94.974 ; R52.2@56.092,109.615 v1(56.857,109.615) 56.856,109.616 v1(56.856,110.364) ; R52.2@56.092,109.615 56.092,110.114 ; 56.092,110.114 R51.2@56.092,111.227 ; 56.092,110.114 56.341,110.364 v1(56.856,110.364) ; R51.2@56.092,111.227 56.856,110.463 v1(56.856,110.364) ; v1@66.832,19.676 68.26,19.676 C41.1@68.318,19.734 68.293,19.734 68.081,19.946 68.081,20.925 ; v1@66.832,19.676 v1(67.424,20.268) 68.081,20.925 ; 73.499,14.168 v1(72.68,13.349) 72.68,13.911 v1(72.466,14.125) 72.508,14.168 73.499,14.168
  Bottom Layer w0.508: v1(34.768,37.642) 35.78,38.653 45.196,38.653 46.822,37.027 R13.2@46.822,35.774 ; R13.2@46.97,35.774 47.181,35.563 47.614,35.563 v1(50.128,33.049) ; v1(53.241,20.886) 54.872,20.886 58.85,24.864 v1(58.85,34.138) 56.474,36.513 R33.1@55.584,36.513
  Bottom Layer w0.762: P1.34@4.621,46.74 P1.32@4.621,49.28 P1.30@4.621,51.82 ; v1(13.534,97.216) 13.534,93.646 15.607,91.572 v1(15.607,88.182) v1(15.607,87.351) 15.607,71.917 11.488,67.798 v1(11.488,43.718) 11.488,40.463 8.534,37.51 8.534,7.911 12.129,4.316 26.772,4.316 ; v1(20.469,40.683) 20.484,40.683 20.631,40.536 21.105,40.536 v1(21.26,40.691) v1@20.476,40.691 ; 20.659,40.09 20.469,39.9 20.469,27.387 27.792,20.063 27.792,5.336 ; C23.2@35.694,27.34 v1(36.646,27.34) 37.141,27.836 42.424,27.836 v1(43.021,27.239) ; C24.2@36.628,35.938 C22.2@38.206,35.938 C28.2@40.521,35.938 C27.2@42.099,35.938 ; v1(56.856,110.364) 56.857,110.363 v1(56.857,109.615) 56.857,102.342 58.333,100.865 58.333,95.831 ; v1(66.778,19.676) v1@66.986,19.468 ; 67.193,19.261 67.193,20.038 v1(67.424,20.268) ; 67.424,19.03 v1@72.397,14.057 ; v1@72.624,13.83 72.624,5.111 69.289,1.777 30.332,1.777 27.792,4.316 ; 26.772,4.316 27.792,4.316 ; 26.772,4.316 27.792,5.336 ; 27.792,4.316 27.792,5.336 ; 58.333,95.831 v1(59.096,95.069) 58.428,95.069 v1(58.333,94.974) 58.333,95.831
  other v1: 39.816,36.257 11.497,42.919
5V: C40.1 P2.9 P2.10 S2.2 U4.3 | length 71.8
  Top Layer w1.016: U4.3@70.381,22.254 70.381,19.915 C40.1@70.563,19.734 72.452,19.734 74.789,22.071 76.368,22.071 S2.2@76.403,22.106
  Bottom Layer w1.016: S2.2@76.403,22.106 76.368,22.141 75.003,22.141 72.262,24.882 72.262,75.696 73.786,77.22 P2.9@75.379,77.22 P2.10@77.919,77.22
AVDD10: C1.2 C2.2 C3.2 C4.2 C5.2 C6.2 L1.2 U1.4 U1.9 U1.22 U1.47 | length 27.4
  Top Layer w0.203: v1(35.463,28.729) 35.539,28.729 35.896,29.086 U1.47@37.1,29.086 ; v2(38.988,28.853) 38.997,28.844 38.997,27.99 U1.4@39,27.986 ; U1.9@40.997,27.99 v2@40.997,28.844 ; U1.22@42.9,32.286 43.946,32.286 44.209,32.55 v1(44.347,32.55)
  Bottom Layer w0.203: v1(35.463,28.729) 35.463,29.275 C1.2@35.709,29.521
  Bottom Layer w0.508: C1.2@35.903,29.563 38.837,29.563 C3.2@38.953,29.447 ; C3.2@39.073,29.447 C2.2@40.623,29.447 ; C2.2@40.859,29.658 C2.2@41.093,29.658
  Bottom Layer w0.762: C2.2@40.623,29.447 42.699,29.447 42.993,29.153 44.462,29.153 44.468,29.147 44.571,29.147 C4.2@46.342,29.147 ; v1(44.347,32.55) 44.516,32.381 45.349,32.381 C6.2@45.433,32.297 46.529,32.297 47.056,31.769 47.056,29.836 ; C4.2@46.342,29.147 46.4,29.09 C5.2@47.957,29.09 ; C4.2@46.342,29.147 C4.2@46.367,29.147 ; C4.2@46.367,29.147 47.056,29.147 47.056,29.836 ; C4.2@46.367,29.147 47.056,29.836 ; 47.056,29.836 47.211,29.836 C5.2@47.957,29.09 ; C5.2@47.957,29.09 48.112,29.09 48.17,29.032 48.015,29.032 C5.2@47.957,29.09
  other v2: 40.988,28.853
BOOT0: P1.37 U3.94 | length 59.7
  Top Layer w0.178: v1(10.516,71.603) 11.163,70.955 21.667,70.955 23.069,72.357 27.422,72.357 28.245,71.534 30.755,71.534 30.998,71.291 U3.94@32.222,70.068
  Bottom Layer w0.178: P1.37@2.081,41.66 3.331,42.91 8.088,42.91 10.516,45.337 v1(10.516,71.603)
BOOT1: P1.38 U3.37 | length 65.2
  Top Layer w0.203: P1.38@4.621,41.66 7.032,41.66 11.633,37.059 23.37,37.059 24.701,35.728 24.714,35.728 24.882,35.56 v1(25.019,35.56) ; U3.37@45.303,60.522 47.152,58.673 v1(47.152,57.919)
  Bottom Layer w0.203: v1(25.019,35.56) 25.019,48.36 30.186,53.527 37.163,53.527 41.555,57.919 v1(47.152,57.919)
DP_PWDN: P10.18 S4.1 U3.7 | length 116.5
  Top Layer w0.203: v1(25.37,62.207) 26.794,60.784 27.901,60.784 29.137,62.019 31.245,62.019 U3.7@32.222,62.996 ; P10.18@29.84,110.007 32.516,107.331 44.463,107.331 51.861,99.934 68.132,99.934 70.626,97.439 S4.1@70.626,91.182
  Bottom Layer w0.203: v1(25.37,62.207) 25.37,63.862 22.667,66.565 22.667,75.167 17.801,80.034 17.801,97.742 29.84,109.781 P10.18@29.84,110.007
DP_RESET: P10.7 S7.1 U3.53 | length 114.5
  Top Layer w0.203: P10.7@42.54,112.547 43.772,111.315 43.772,108.625 51.891,100.506 70.803,100.506 S7.1@73.126,98.183 ; v1(45.992,67.431) 47.97,67.431 U3.53@49.192,68.653
  Bottom Layer w0.203: P10.7@42.54,112.547 44.144,114.151 52.165,114.151 54.171,112.145 54.171,102.302 57.057,99.417 57.057,85.807 54.188,82.938 45.596,82.938 42.445,79.787 42.445,69.095 44.108,67.431 v1(45.992,67.431)
DVDDREG: C8.2 C9.2 R13.1 U1.29 | length 7.7
  Top Layer w0.178: v1@40.6,32.892 U1.29@40.6,33.786
  Bottom Layer w0.762: v1@40.657,32.867 41.815,34.024 43.329,34.024 43.455,34.15 43.689,34.15 C8.2@43.773,34.234 ; C8.2@43.798,34.234 C9.2@45.357,34.234 R13.1@46.97,34.234
  other v1: 40.6,32.867
DVP_D2/SDIO_D0: P7.7 P10.10 R20.1 U3.65 | length 87.9
  Top Layer w0.203: v1(23.063,85.496) 35.866,85.496 36.952,84.41 46.246,84.41 49.544,81.112 49.544,77.49 U3.65@44.95,72.896 ; R20.1@26.192,99.213 30.816,99.213 32.42,99.213 35.008,101.801 P7.7@38.25,101.801
  Bottom Layer w0.203: v1(23.063,85.496) 23.063,91.583 29.598,98.118 ; 29.566,98.118 29.598,98.118 ; P10.10@40,110.007 40,105.773 37.177,102.95 36.715,102.488 cw(c36.554,102.65) 36.392,102.488 36.369,102.511 ccw(c36.208,102.349) 36.046,102.511 ccw(c36.208,102.349) 36.046,102.188 36.316,101.918 cw(c36.154,101.756) 36.316,101.595 cw(c36.154,101.756) 35.992,101.595 35.723,101.864 ccw(c35.561,101.703) 35.399,101.864 ccw(c35.561,101.703) 35.399,101.541 35.669,101.271 cw(c35.508,101.11) 35.346,100.948 35.076,101.218 ccw(c34.915,101.056) 34.753,101.218 ccw(c34.915,101.056) 34.753,100.894 34.775,100.872 cw(c34.614,100.71) 34.775,100.549 34.704,100.477 33.69,99.463 30.944,99.463 29.598,98.118
  other v1: 30.816,99.249
DVP_D3/SDIO_D1: P7.8 P10.11 R18.1 U3.66 | length 87.6
  Top Layer w0.203: v1(20.777,84.734) 35.883,84.734 36.623,83.995 46.158,83.995 49.188,80.965 49.188,77.842 U3.66@44.596,73.25 ; R18.1@26.192,100.926 28.906,100.926 29.257,101.277 v1(29.345,101.277) 30.968,102.901 P7.8@38.25,102.901
  Bottom Layer w0.203: v1(20.777,84.734) 20.777,92.786 29.478,101.487 29.478,101.839 35.45,107.81 35.852,107.81 36.155,108.113 36.155,111.55 37.153,112.547 P10.11@37.46,112.547
DVP_D4/SDIO_D3: P7.2 P10.12 R8.1 U3.79 | length 88.6
  Top Layer w0.203: v1(21.641,81.737) 21.707,81.803 31.093,81.803 U3.79@37.525,75.371 ; v1(25.348,96.275) 25.828,95.795 25.828,95.575 R8.1@26.192,95.212 29.517,95.212 30.606,96.301 P7.2@38.25,96.301
  Bottom Layer w0.203: v1(21.641,81.737) 21.641,92.606 30.268,101.233 30.34,101.305 ccw(c30.16,101.484) 30.34,101.664 30.262,101.742 cw(c30.442,101.921) 30.621,102.101 31.503,101.22 ccw(c31.682,101.399) 31.862,101.22 ccw(c31.682,101.399) 31.862,101.579 30.981,102.46 cw(c31.16,102.64) 30.981,102.819 cw(c31.16,102.64) 31.34,102.819 32.221,101.938 ccw(c32.401,102.118) 32.58,102.297 31.699,103.178 cw(c31.879,103.358) 31.699,103.538 cw(c31.879,103.358) 32.058,103.538 32.94,102.656 ccw(c33.119,102.836) 33.299,102.656 ccw(c33.119,102.836) 33.299,103.016 32.418,103.897 cw(c32.597,104.076) 32.777,104.256 33.658,103.375 ccw(c33.838,103.554) 34.017,103.375 ccw(c33.838,103.554) 34.017,103.734 33.136,104.615 cw(c33.316,104.795) 33.136,104.975 cw(c33.316,104.795) 33.495,104.975 34.376,104.093 ccw(c34.556,104.273) 34.736,104.453 33.854,105.334 cw(c34.034,105.513) 33.854,105.693 cw(c34.034,105.513) 34.214,105.693 35.095,104.812 ccw(c35.274,104.991) 35.454,104.812 ccw(c35.274,104.991) 35.454,105.171 34.573,106.052 cw(c34.752,106.232) 34.932,106.411 35.813,105.53 ccw(c35.993,105.71) 36.172,105.53 ccw(c35.993,105.71) 36.172,105.889 35.728,106.334 cw(c35.908,106.513) 35.728,106.693 36.069,107.033 37.46,108.425 P10.12@37.46,110.007
DVP_D5: P10.13 R53.2 | length 70.8
  Top Layer w0.203: v1(25.03,74.46) 25.045,74.444 29.666,74.444 R53.2@30.378,73.732
  Bottom Layer w0.203: 24.3,98.87 ccw(c24.452,99.023) 24.605,98.87 ccw(c24.452,99.023) 24.605,99.175 24.261,99.519 cw(c24.413,99.672) 24.566,99.825 24.91,99.481 ccw(c25.063,99.633) 25.216,99.786 24.871,100.13 cw(c25.024,100.283) 25.177,100.435 25.521,100.091 ccw(c25.674,100.244) 25.826,100.397 25.482,100.741 cw(c25.635,100.893) 25.787,101.046 26.132,100.702 ccw(c26.284,100.855) 26.437,101.007 26.093,101.351 cw(c26.245,101.504) 26.093,101.657 cw(c26.245,101.504) 26.398,101.657 26.742,101.313 ccw(c26.895,101.465) 27.048,101.618 26.703,101.962 cw(c26.856,102.115) 27.009,102.267 27.353,101.923 ccw(c27.506,102.076) 27.658,102.229 27.314,102.573 cw(c27.467,102.725) 27.619,102.878 27.964,102.534 ccw(c28.116,102.687) 28.269,102.839 27.925,103.183 cw(c28.077,103.336) 27.925,103.489 cw(c28.077,103.336) 28.23,103.489 28.574,103.145 ccw(c28.727,103.297) 28.88,103.45 28.535,103.794 cw(c28.688,103.947) 28.841,104.099 29.185,103.755 ccw(c29.338,103.908) 29.49,104.061 29.146,104.405 cw(c29.299,104.557) 29.451,104.71 29.796,104.366 ccw(c29.948,104.519) 30.101,104.671 29.757,105.015 cw(c29.909,105.168) 30.062,105.321 30.135,105.248 ccw(c30.288,105.4) 30.441,105.248 30.712,105.519 33.668,108.475 33.668,110.707 33.664,110.71 33.664,111.292 P10.13@34.92,112.547 ; 24.3,98.87 23.955,99.214 ccw(c23.803,99.061) 23.65,98.909 23.994,98.565 cw(c23.842,98.412) 23.689,98.259 23.345,98.603 ccw(c23.192,98.451) 23.04,98.298 23.384,97.954 cw(c23.231,97.801) 23.078,97.649 22.734,97.993 ccw(c22.582,97.84) 22.429,97.687 22.502,97.614 cw(c22.349,97.462) 22.502,97.309 22.43,97.237 19.334,94.141 19.334,81.27 25.03,75.574 v1(25.03,74.46)
DVP_D6: P10.14 U3.95 | length 74.8
  Top Layer w0.203: v1(25.692,71.642) 26.166,71.168 30.414,71.168 U3.95@31.868,69.714
  Bottom Layer w0.203: v1(25.692,71.642) 25.692,75.564 19.838,81.417 19.838,93.451 19.96,93.572 20.337,93.949 cw(c20.489,93.797) 20.642,93.949 20.669,93.923 ccw(c20.822,94.075) 20.974,94.228 20.693,94.509 cw(c20.846,94.661) 20.999,94.814 21.28,94.533 ccw(c21.432,94.686) 21.585,94.839 21.304,95.119 cw(c21.457,95.272) 21.609,95.425 21.89,95.144 ccw(c22.043,95.297) 22.196,95.144 ccw(c22.043,95.297) 22.196,95.449 21.915,95.73 cw(c22.067,95.883) 22.22,96.035 22.501,95.755 ccw(c22.654,95.907) 22.806,96.06 22.525,96.341 cw(c22.678,96.493) 22.831,96.646 23.111,96.365 ccw(c23.264,96.518) 23.417,96.671 23.273,96.814 cw(c23.426,96.967) 23.578,97.12 23.722,96.976 ccw(c23.875,97.129) 24.027,97.281 23.891,97.417 cw(c24.044,97.57) 23.891,97.723 cw(c24.044,97.57) 24.197,97.723 24.333,97.587 ccw(c24.485,97.739) 24.638,97.892 24.611,97.919 cw(c24.764,98.071) 24.611,98.224 26.443,100.056 cw(c26.596,99.903) 26.749,100.056 26.775,100.029 ccw(c26.928,100.182) 27.081,100.335 26.942,100.474 cw(c27.094,100.626) 27.247,100.779 27.386,100.64 ccw(c27.539,100.792) 27.691,100.945 27.552,101.085 cw(c27.704,101.238) 27.857,101.39 27.997,101.25 ccw(c28.149,101.403) 28.302,101.25 ccw(c28.149,101.403) 28.302,101.556 28.162,101.696 cw(c28.314,101.849) 28.467,102.001 28.607,101.861 ccw(c28.76,102.014) 28.913,102.166 28.772,102.307 cw(c28.924,102.46) 29.077,102.613 29.218,102.472 ccw(c29.371,102.624) 29.523,102.777 29.382,102.919 cw(c29.535,103.071) 29.687,103.224 29.829,103.082 ccw(c29.981,103.235) 30.134,103.082 ccw(c29.981,103.235) 30.134,103.388 29.992,103.53 cw(c30.145,103.683) 30.297,103.835 30.439,103.693 ccw(c30.592,103.846) 30.745,103.998 30.602,104.141 cw(c30.755,104.294) 30.907,104.446 31.05,104.304 ccw(c31.203,104.456) 31.355,104.609 31.075,104.89 cw(c31.227,105.043) 31.38,105.195 31.661,104.914 ccw(c31.813,105.067) 31.966,105.22 31.685,105.501 cw(c31.838,105.653) 31.685,105.806 cw(c31.838,105.653) 31.991,105.806 32.271,105.525 ccw(c32.424,105.678) 32.577,105.83 32.296,106.111 cw(c32.449,106.264) 32.601,106.417 32.882,106.136 ccw(c33.035,106.288) 33.187,106.441 32.907,106.722 cw(c33.059,106.875) 33.212,107.027 33.493,106.746 ccw(c33.645,106.899) 33.798,107.052 33.517,107.333 cw(c33.67,107.485) 33.823,107.638 34.103,107.357 ccw(c34.256,107.51) 34.409,107.357 ccw(c34.256,107.51) 34.409,107.662 34.382,107.689 cw(c34.535,107.842) 34.382,107.994 34.619,108.232 34.92,108.533 P10.14@34.92,110.007
DVP_D7: P10.15 U3.96 | length 74.7
  Top Layer w0.203: v1(23.388,71.261) 23.92,70.729 30.146,70.729 U3.96@31.515,69.36
  Bottom Layer w0.203: v1(23.388,71.261) 23.388,71.3 23.084,71.604 23.084,75.799 18.267,80.616 18.267,95.943 19.181,96.857 19.576,97.252 cw(c19.738,97.09) 19.899,97.252 19.993,97.158 ccw(c20.155,97.32) 20.317,97.481 20.038,97.76 cw(c20.199,97.922) 20.038,98.084 cw(c20.199,97.922) 20.361,98.084 20.64,97.804 ccw(c20.802,97.966) 20.963,97.804 ccw(c20.802,97.966) 20.963,98.128 20.684,98.407 cw(c20.846,98.569) 20.684,98.73 cw(c20.846,98.569) 21.007,98.73 21.287,98.451 ccw(c21.448,98.613) 21.61,98.451 ccw(c21.448,98.613) 21.61,98.774 21.331,99.053 cw(c21.492,99.215) 21.654,99.377 21.933,99.098 ccw(c22.095,99.259) 22.256,99.098 ccw(c22.095,99.259) 22.256,99.421 21.977,99.7 cw(c22.139,99.862) 21.977,100.023 cw(c22.139,99.862) 22.301,100.023 22.58,99.744 ccw(c22.741,99.906) 22.903,99.744 ccw(c22.741,99.906) 22.903,100.067 22.624,100.347 cw(c22.785,100.508) 22.947,100.67 23.226,100.391 ccw(c23.388,100.552) 23.55,100.391 ccw(c23.388,100.552) 23.55,100.714 23.27,100.993 cw(c23.432,101.155) 23.27,101.317 cw(c23.432,101.155) 23.594,101.317 23.873,101.037 ccw(c24.035,101.199) 24.196,101.037 ccw(c24.035,101.199) 24.196,101.361 23.917,101.64 cw(c24.079,101.801) 23.917,101.963 cw(c24.079,101.801) 24.24,101.963 24.519,101.684 ccw(c24.681,101.846) 24.843,102.007 24.564,102.286 cw(c24.725,102.448) 24.564,102.61 cw(c24.725,102.448) 24.887,102.61 25.166,102.331 ccw(c25.328,102.492) 25.489,102.331 ccw(c25.328,102.492) 25.489,102.654 25.21,102.933 cw(c25.372,103.095) 25.21,103.256 cw(c25.372,103.095) 25.533,103.256 25.813,102.977 ccw(c25.974,103.139) 26.136,103.3 25.857,103.58 cw(c26.018,103.741) 25.857,103.903 cw(c26.018,103.741) 26.18,103.903 26.459,103.624 ccw(c26.621,103.785) 26.782,103.624 ccw(c26.621,103.785) 26.782,103.947 26.503,104.226 cw(c26.665,104.388) 26.503,104.549 cw(c26.665,104.388) 26.827,104.549 27.106,104.27 ccw(c27.267,104.432) 27.429,104.27 ccw(c27.267,104.432) 27.429,104.594 27.15,104.873 cw(c27.312,105.034) 27.473,105.196 27.752,104.917 ccw(c27.914,105.078) 28.076,104.917 ccw(c27.914,105.078) 28.076,105.24 27.981,105.334 cw(c28.143,105.496) 27.981,105.658 28.368,106.044 31.007,108.684 31.007,108.737 31.007,111.175 P10.15@32.38,112.547
DVP_HSYNC: P10.5 U3.29 | length 74.7
  Top Layer w0.203: v1(38.735,59.957) 40.211,59.957 U3.29@42.475,57.693
  Bottom Layer w0.203: v1(38.735,59.957) 37.969,60.723 37.969,77.751 44.578,84.36 52.851,84.36 55.113,86.622 55.113,95.312 43.911,106.514 43.911,111.378 P10.5@45.08,112.547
